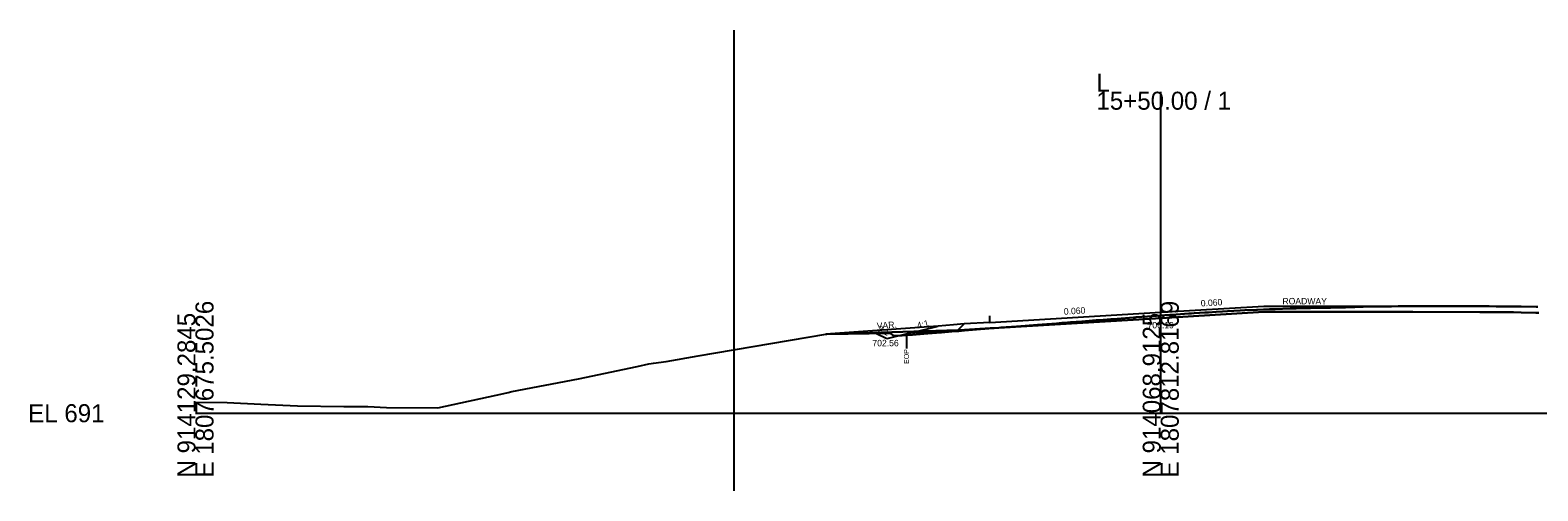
# Model space of a CAD drawing. Extents: x -26 to 1352, y -510 to 9596.
# Drawn here: x -25.7 to 208.6, y 1487.9 to 1559.6 of the extents above; entities that cross this region are included whole.
import ezdxf

# ---------------------------------------------------------------- set-up
doc = ezdxf.new("R2010")
doc.units = 0
for name, color, linetype in [('Exist Cross Section Cell', 7, 'Continuous'), ('Exist XS Center Line Elevation Label', 7, 'Continuous'), ('Exist XS Ground Line', 7, 'Continuous'), ('Old_Level_10', 7, 'Continuous'), ('Prop XS Ditch Slope Text', 7, 'Continuous'), ('Prop XS Earthwork Shape', 7, 'Continuous'), ('Prop XS EOT Tick Mark', 7, 'Continuous'), ('Prop XS Exc Vertical Line 1', 7, 'Continuous'), ('Prop XS Finish Grade', 7, 'Continuous'), ('Prop XS Finish Grade Paved Shoulder', 7, 'Continuous'), ('Prop XS Finish Grade Pavement', 7, 'Continuous'), ('Prop XS Pvmt Edge Slope', 7, 'Continuous'), ('Prop XS SE Text', 7, 'Continuous'), ('Prop XS Subgrade Earthwork', 7, 'Continuous'), ('Scratch_Level_0', 7, 'Continuous')]:
    doc.layers.add(name, color=color, linetype=linetype)

msp = doc.modelspace()

# ---------------------------------------------------------------- linework, layer by layer
at = {"layer": 'Exist Cross Section Cell'}
for p, q in [((150, 1500), (150, 1550)), ((0, 1500), (150, 1500)), ((150, 1500), (300, 1500))]:
    msp.add_line(p, q, dxfattribs=at)
at = {"layer": 'Exist XS Ground Line'}
msp.add_lwpolyline([(0, 1501.72), (4.91, 1501.68), (10.16, 1501.4), (15.84, 1501.17), (23.07, 1501.03), (26.76, 1501.04), (29.66, 1500.91), (37.68, 1500.84), (47.91, 1503.08), (48.61, 1503.23), (49.15, 1503.36), (59.53, 1505.33), (68.65, 1507.25), (70.46, 1507.66), (71.16, 1507.76), (73.15, 1508.03), (78.11, 1508.9), (97.94, 1512.28), (98.11, 1512.28), (108, 1512.43), (108.13, 1512.32), (108.5, 1512.03), (109.81, 1512.08), (110.48, 1512.12), (111.4, 1512.19), (113.17, 1512.32), (113.78, 1512.37), (115.16, 1512.49), (115.91, 1512.55), (117.56, 1512.69), (118.63, 1512.78), (119.48, 1512.85), (121.37, 1513.01), (121.39, 1513.01), (123.26, 1513.16), (124.09, 1513.22), (125.15, 1513.31), (126.82, 1513.44), (127.58, 1513.5), (128.95, 1513.61), (129.56, 1513.66), (130.85, 1513.76), (132.29, 1513.86), (133.78, 1513.97), (134.64, 1514.04), (135.02, 1514.06), (135.98, 1514.14), (137.75, 1514.27), (139.99, 1514.45), (140.33, 1514.48), (140.48, 1514.49), (142.23, 1514.62), (143.21, 1514.69), (145.75, 1514.88), (145.95, 1514.89), (146.02, 1514.9), (146.2, 1514.91), (147.92, 1515.04), (148.68, 1515.09), (150, 1515.19), (150.62, 1515.24), (151.41, 1515.3), (151.71, 1515.32), (152.41, 1515.37), (154.39, 1515.51), (154.76, 1515.53), (155.17, 1515.55), (156.86, 1515.64), (157.4, 1515.68), (158.63, 1515.76), (159.6, 1515.82), (160.37, 1515.86), (162.33, 1515.97), (163.09, 1516.01), (164.87, 1516.08), (165, 1516.09), (165.06, 1516.09), (166.9, 1516.16), (167.8, 1516.19), (170.11, 1516.26), (170.52, 1516.28), (171.06, 1516.29), (172.59, 1516.33), (173.26, 1516.34), (174.97, 1516.38), (175.99, 1516.4), (176.38, 1516.41), (177.27, 1516.43), (178.27, 1516.45), (178.71, 1516.46), (180.18, 1516.51), (181.45, 1516.53), (183.48, 1516.58), (184.18, 1516.59), (185.87, 1516.62), (186.91, 1516.64), (189.58, 1516.66), (189.63, 1516.66), (189.7, 1516.66), (192.37, 1516.67), (194.47, 1516.66), (195.1, 1516.66), (195.91, 1516.66), (197.24, 1516.65), (197.82, 1516.65), (199.14, 1516.64), (200.56, 1516.63), (201.04, 1516.63), (202.11, 1516.62), (202.93, 1516.62), (203.29, 1516.62), (204.84, 1516.6), (206.03, 1516.59), (208.32, 1516.54), (208.62, 1516.54)], dxfattribs=at)
at = {"layer": 'Old_Level_10'}
msp.add_line((110.48, 1512.12), (110.48, 1510.07), dxfattribs=at)
at = {"layer": 'Prop XS Earthwork Shape'}
for points in [[(208.62, 1516.54), (208.32, 1516.54), (206.03, 1516.59), (204.84, 1516.6), (203.29, 1516.62), (202.93, 1516.62), (202.11, 1516.62), (201.04, 1516.63), (200.56, 1516.63), (199.14, 1516.64), (197.82, 1516.65), (197.24, 1516.65), (195.91, 1516.66), (195.1, 1516.66), (194.47, 1516.66), (192.37, 1516.67), (189.7, 1516.66), (189.63, 1516.66), (189.58, 1516.66), (186.91, 1516.64), (185.87, 1516.62), (184.18, 1516.59), (183.48, 1516.58), (181.45, 1516.53), (180.18, 1516.51), (178.71, 1516.46), (178.27, 1516.45), (177.27, 1516.43), (176.38, 1516.41), (175.99, 1516.4), (174.97, 1516.38), (173.26, 1516.34), (172.59, 1516.33), (171.06, 1516.29), (170.52, 1516.28), (170.11, 1516.26), (167.8, 1516.19), (166.9, 1516.16), (165.06, 1516.09), (165, 1516.09), (164.87, 1516.08), (163.09, 1516.01), (162.33, 1515.97), (160.37, 1515.86), (159.6, 1515.82), (158.63, 1515.76), (157.4, 1515.68), (156.86, 1515.64), (155.17, 1515.55), (154.76, 1515.53), (154.39, 1515.51), (152.41, 1515.37), (151.71, 1515.32), (151.41, 1515.3), (150.62, 1515.24), (150, 1515.19), (148.68, 1515.09), (147.92, 1515.04), (146.2, 1514.91), (146.02, 1514.9), (145.95, 1514.89), (145.75, 1514.88), (143.21, 1514.69), (142.23, 1514.62), (140.48, 1514.49), (140.33, 1514.48), (139.99, 1514.45), (137.75, 1514.27), (135.98, 1514.14), (135.02, 1514.06), (134.64, 1514.04), (133.78, 1513.97), (132.29, 1513.86), (130.85, 1513.76), (129.56, 1513.66), (128.95, 1513.61), (127.58, 1513.5), (126.82, 1513.44), (125.15, 1513.31), (124.83, 1513.28), (150.05, 1514.79), (166.03, 1515.75), (189.15, 1515.75), (199.58, 1515.73), (201.25, 1515.71), (203.28, 1515.7), (204.82, 1515.69), (206.01, 1515.67), (208.3, 1515.63), (208.6, 1515.62), (208.74, 1515.62)], [(208.62, 1516.54), (208.32, 1516.54), (206.03, 1516.59), (204.84, 1516.6), (203.29, 1516.62), (202.93, 1516.62), (202.11, 1516.62), (201.04, 1516.63), (200.56, 1516.63), (199.14, 1516.64), (197.82, 1516.65), (197.24, 1516.65), (195.91, 1516.66), (195.1, 1516.66), (194.47, 1516.66), (192.37, 1516.67), (189.7, 1516.66), (189.63, 1516.66), (189.58, 1516.66), (186.91, 1516.64), (185.87, 1516.62), (184.18, 1516.59), (183.48, 1516.58), (181.45, 1516.53), (180.18, 1516.51), (178.71, 1516.46), (178.27, 1516.45), (177.27, 1516.43), (176.38, 1516.41), (175.99, 1516.4), (174.97, 1516.38), (173.26, 1516.34), (172.59, 1516.33), (171.06, 1516.29), (170.52, 1516.28), (170.11, 1516.26), (167.8, 1516.19), (166.9, 1516.16), (165.06, 1516.09), (165, 1516.09), (164.87, 1516.08), (163.09, 1516.01), (162.33, 1515.97), (160.37, 1515.86), (159.6, 1515.82), (158.63, 1515.76), (157.4, 1515.68), (156.86, 1515.64), (155.17, 1515.55), (154.76, 1515.53), (154.39, 1515.51), (152.41, 1515.37), (151.71, 1515.32), (151.41, 1515.3), (150.62, 1515.24), (150, 1515.19), (148.68, 1515.09), (147.92, 1515.04), (146.2, 1514.91), (146.02, 1514.9), (145.95, 1514.89), (145.75, 1514.88), (143.21, 1514.69), (142.23, 1514.62), (140.48, 1514.49), (140.33, 1514.48), (139.99, 1514.45), (137.75, 1514.27), (135.98, 1514.14), (135.02, 1514.06), (134.64, 1514.04), (133.78, 1513.97), (132.29, 1513.86), (130.85, 1513.76), (129.56, 1513.66), (128.95, 1513.61), (127.58, 1513.5), (126.82, 1513.44), (125.15, 1513.31), (124.83, 1513.28), (150.05, 1514.79), (166.03, 1515.75), (189.15, 1515.75), (199.58, 1515.73), (201.25, 1515.71), (203.28, 1515.7), (204.82, 1515.69), (206.01, 1515.67), (208.3, 1515.63), (208.6, 1515.62), (208.74, 1515.62)], [(208.74, 1515.62), (208.6, 1515.62), (208.3, 1515.63), (206.01, 1515.67), (204.82, 1515.69), (203.28, 1515.7), (201.25, 1515.71), (199.58, 1515.73), (189.15, 1515.75), (166.03, 1515.75), (150.05, 1514.79), (124.83, 1513.28), (125.15, 1513.31), (126.82, 1513.44), (127.58, 1513.5), (128.95, 1513.61), (129.56, 1513.66), (130.85, 1513.76), (132.29, 1513.86), (133.78, 1513.97), (134.64, 1514.04), (135.02, 1514.06), (135.98, 1514.14), (137.75, 1514.27), (139.99, 1514.45), (140.33, 1514.48), (140.48, 1514.49), (142.23, 1514.62), (143.21, 1514.69), (145.75, 1514.88), (145.95, 1514.89), (146.02, 1514.9), (146.2, 1514.91), (147.92, 1515.04), (148.68, 1515.09), (150, 1515.19), (150.62, 1515.24), (151.41, 1515.3), (151.71, 1515.32), (152.41, 1515.37), (154.39, 1515.51), (154.76, 1515.53), (155.17, 1515.55), (156.86, 1515.64), (157.4, 1515.68), (158.63, 1515.76), (159.6, 1515.82), (160.37, 1515.86), (162.33, 1515.97), (163.09, 1516.01), (164.87, 1516.08), (165, 1516.09), (165.06, 1516.09), (166.9, 1516.16), (167.8, 1516.19), (170.11, 1516.26), (170.52, 1516.28), (171.06, 1516.29), (172.59, 1516.33), (173.26, 1516.34), (174.97, 1516.38), (175.99, 1516.4), (176.38, 1516.41), (177.27, 1516.43), (178.27, 1516.45), (178.71, 1516.46), (180.18, 1516.51), (181.45, 1516.53), (183.48, 1516.58), (184.18, 1516.59), (185.87, 1516.62), (186.91, 1516.64), (189.58, 1516.66), (189.63, 1516.66), (189.7, 1516.66), (192.37, 1516.67), (194.47, 1516.66), (195.1, 1516.66), (195.91, 1516.66), (197.24, 1516.65), (197.82, 1516.65), (199.14, 1516.64), (200.56, 1516.63), (201.04, 1516.63), (202.11, 1516.62), (202.93, 1516.62), (203.29, 1516.62), (204.84, 1516.6), (206.03, 1516.59), (208.32, 1516.54), (208.62, 1516.54)], [(208.74, 1515.62), (208.6, 1515.62), (208.3, 1515.63), (206.01, 1515.67), (204.82, 1515.69), (203.28, 1515.7), (201.25, 1515.71), (199.58, 1515.73), (189.15, 1515.75), (166.03, 1515.75), (150.05, 1514.79), (124.83, 1513.28), (125.15, 1513.31), (126.82, 1513.44), (127.58, 1513.5), (128.95, 1513.61), (129.56, 1513.66), (130.85, 1513.76), (132.29, 1513.86), (133.78, 1513.97), (134.64, 1514.04), (135.02, 1514.06), (135.98, 1514.14), (137.75, 1514.27), (139.99, 1514.45), (140.33, 1514.48), (140.48, 1514.49), (142.23, 1514.62), (143.21, 1514.69), (145.75, 1514.88), (145.95, 1514.89), (146.02, 1514.9), (146.2, 1514.91), (147.92, 1515.04), (148.68, 1515.09), (150, 1515.19), (150.62, 1515.24), (151.41, 1515.3), (151.71, 1515.32), (152.41, 1515.37), (154.39, 1515.51), (154.76, 1515.53), (155.17, 1515.55), (156.86, 1515.64), (157.4, 1515.68), (158.63, 1515.76), (159.6, 1515.82), (160.37, 1515.86), (162.33, 1515.97), (163.09, 1516.01), (164.87, 1516.08), (165, 1516.09), (165.06, 1516.09), (166.9, 1516.16), (167.8, 1516.19), (170.11, 1516.26), (170.52, 1516.28), (171.06, 1516.29), (172.59, 1516.33), (173.26, 1516.34), (174.97, 1516.38), (175.99, 1516.4), (176.38, 1516.41), (177.27, 1516.43), (178.27, 1516.45), (178.71, 1516.46), (180.18, 1516.51), (181.45, 1516.53), (183.48, 1516.58), (184.18, 1516.59), (185.87, 1516.62), (186.91, 1516.64), (189.58, 1516.66), (189.63, 1516.66), (189.7, 1516.66), (192.37, 1516.67), (194.47, 1516.66), (195.1, 1516.66), (195.91, 1516.66), (197.24, 1516.65), (197.82, 1516.65), (199.14, 1516.64), (200.56, 1516.63), (201.04, 1516.63), (202.11, 1516.62), (202.93, 1516.62), (203.29, 1516.62), (204.84, 1516.6), (206.03, 1516.59), (208.32, 1516.54), (208.62, 1516.54)]]:
    msp.add_lwpolyline(points, dxfattribs=at)
for points in [[(123.48, 1513.2), (124.83, 1513.28), (124.09, 1513.22), (123.26, 1513.16), (121.39, 1513.01), (121.37, 1513.01), (119.48, 1512.85), (118.63, 1512.78), (117.56, 1512.69), (115.91, 1512.55), (115.16, 1512.49), (113.78, 1512.37), (113.17, 1512.32), (111.4, 1512.19), (110.48, 1512.12), (109.81, 1512.08), (108.5, 1512.03), (108.13, 1512.32), (108, 1512.43), (98.11, 1512.28), (97.94, 1512.28), (118.45, 1512.9), (119.48, 1512.96)], [(119.48, 1512.96), (118.45, 1512.9), (97.94, 1512.28), (98.11, 1512.28), (108, 1512.43), (108.13, 1512.32), (108.5, 1512.03), (109.81, 1512.08), (110.48, 1512.12), (111.4, 1512.19), (113.17, 1512.32), (113.78, 1512.37), (115.16, 1512.49), (115.91, 1512.55), (117.56, 1512.69), (118.63, 1512.78), (119.48, 1512.85), (121.37, 1513.01), (121.39, 1513.01), (123.26, 1513.16), (124.09, 1513.22), (124.83, 1513.28), (123.48, 1513.2)], [(119.48, 1512.96), (118.45, 1512.9), (97.94, 1512.28), (98.11, 1512.28), (108, 1512.43), (108.13, 1512.32), (108.5, 1512.03), (109.81, 1512.08), (110.48, 1512.12), (111.4, 1512.19), (113.17, 1512.32), (113.78, 1512.37), (115.16, 1512.49), (115.91, 1512.55), (117.56, 1512.69), (118.63, 1512.78), (119.48, 1512.85), (121.37, 1513.01), (121.39, 1513.01), (123.26, 1513.16), (124.09, 1513.22), (124.83, 1513.28), (123.48, 1513.2)], [(118.45, 1512.9), (97.94, 1512.28), (98.11, 1512.28), (108, 1512.43), (108.13, 1512.32), (108.5, 1512.03), (109.81, 1512.08), (110.48, 1512.12), (111.4, 1512.19), (113.17, 1512.32), (113.78, 1512.37), (115.16, 1512.49), (115.91, 1512.55), (117.56, 1512.69), (118.63, 1512.78), (119.48, 1512.85), (121.37, 1513.01), (121.39, 1513.01), (123.26, 1513.16), (124.09, 1513.22), (124.83, 1513.28), (123.48, 1513.2), (119.48, 1512.96)], [(119.48, 1512.96), (118.45, 1512.9), (97.94, 1512.28), (98.11, 1512.28), (108, 1512.43), (108.13, 1512.32), (108.5, 1512.03), (109.81, 1512.08), (110.48, 1512.12), (111.4, 1512.19), (113.17, 1512.32), (113.78, 1512.37), (115.16, 1512.49), (115.91, 1512.55), (117.56, 1512.69), (118.63, 1512.78), (119.48, 1512.85), (121.37, 1513.01), (121.39, 1513.01), (123.26, 1513.16), (124.09, 1513.22), (124.83, 1513.28), (123.48, 1513.2)]]:
    msp.add_lwpolyline(points, close=True, dxfattribs=at)
at = {"layer": 'Prop XS EOT Tick Mark'}
msp.add_line((123.43, 1514.12), (123.43, 1515.12), dxfattribs=at)
at = {"layer": 'Prop XS Exc Vertical Line 1'}
msp.add_line((83.73, 1487.92), (83.73, 1559.58), dxfattribs=at)
at = {"layer": 'Prop XS Finish Grade'}
for p, q in [((115.43, 1513.56), (97.94, 1512.28)), ((117.79, 1513.74), (115.43, 1513.56)), ((119.43, 1513.88), (117.79, 1513.74)), ((111.02, 1512.45), (111.02, 1512.45))]:
    msp.add_line(p, q, dxfattribs=at)
at = {"layer": 'Prop XS Finish Grade Paved Shoulder'}
msp.add_line((123.43, 1514.12), (119.43, 1513.88), dxfattribs=at)
at = {"layer": 'Prop XS Finish Grade Pavement'}
for p, q in [((150, 1515.71), (166, 1516.67)), ((166, 1516.67), (189.15, 1516.67)), ((189.15, 1516.67), (199.15, 1516.64)), ((123.43, 1514.12), (150, 1515.71))]:
    msp.add_line(p, q, dxfattribs=at)
msp.add_lwpolyline([(199.15, 1516.64), (200.56, 1516.63), (201.03, 1516.63), (202.11, 1516.63), (202.93, 1516.62), (203.29, 1516.62), (204.83, 1516.6), (206.02, 1516.59), (208.32, 1516.54), (208.62, 1516.54)], dxfattribs=at)
at = {"layer": 'Prop XS Pvmt Edge Slope'}
msp.add_line((119.43, 1513.88), (118.45, 1512.9), dxfattribs=at)
at = {"layer": 'Prop XS Subgrade Earthwork'}
for p, q in [((123.48, 1513.2), (150.05, 1514.79)), ((150.05, 1514.79), (166.03, 1515.75)), ((166.03, 1515.75), (189.15, 1515.75)), ((189.15, 1515.75), (199.58, 1515.73)), ((199.58, 1515.73), (201.25, 1515.71)), ((118.45, 1512.9), (97.94, 1512.28)), ((119.48, 1512.96), (118.45, 1512.9)), ((123.48, 1513.2), (119.48, 1512.96))]:
    msp.add_line(p, q, dxfattribs=at)
msp.add_lwpolyline([(201.25, 1515.71), (203.28, 1515.7), (204.82, 1515.69), (206.01, 1515.67), (208.3, 1515.63), (208.6, 1515.62)], dxfattribs=at)
at = {"layer": 'Scratch_Level_0'}
for p, q in [((111.02, 1512.45), (115.43, 1513.56)), ((107.43, 1511.56), (105.74, 1512.4)), ((111.02, 1512.45), (107.43, 1511.56)), ((118.45, 1512.9), (111.02, 1512.45))]:
    msp.add_line(p, q, dxfattribs=at)

# ---------------------------------------------------------------- texts
at = {"layer": 'Exist Cross Section Cell'}
for s, p in [('L', (140, 1550)), ('15+50.00 / 1', (140, 1547.2)), ('EL 691', (-26, 1498.6))]:
    msp.add_text(s, height=2.8, dxfattribs=at).set_placement(p)
for s, p in [('E 1807675.5026', (2.8, 1490)), ('E 1807812.8169', (152.8, 1490)), ('N 914129.2845', (0, 1490)), ('N 914068.9125', (150, 1490))]:
    msp.add_text(s, height=2.8, rotation=90, dxfattribs=at).set_placement(p)
at = {"layer": 'Exist XS Center Line Elevation Label'}
msp.add_text('706.19', height=1, dxfattribs=at).set_placement((147.95, 1513.19))
at = {"layer": 'Old_Level_10'}
msp.add_text('EOP', height=0.787, rotation=90, dxfattribs=at).set_placement((110.88, 1507.67))
at = {"layer": 'Prop XS Ditch Slope Text'}
msp.add_text('VAR.', height=1, rotation=3.5821, dxfattribs=at).set_placement((105.9, 1513.1))
at = {"layer": 'Prop XS SE Text'}
for s, rotation, p in [('0.060', 3.4336, (134.97, 1515.31)), ('0.060', 3.4336, (156.25, 1516.59)), ('ROADWAY', 359.688, (168.91, 1516.94))]:
    msp.add_text(s, height=1, rotation=rotation, dxfattribs=at).set_placement(p)
at = {"layer": 'Scratch_Level_0'}
for s, rotation, p in [('2:1', 333.4349, (105.86, 1512.83)), ('4:1', 14.0362, (112.25, 1513.12))]:
    msp.add_text(s, height=1, rotation=rotation, dxfattribs=at).set_placement(p)
msp.add_text('702.56', height=1, dxfattribs=at).set_placement((105.19, 1510.41))

doc.saveas('drawing.dxf')
